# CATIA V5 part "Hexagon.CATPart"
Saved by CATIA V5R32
Part number: Hezagon
Bounding box of the stored display mesh (mm): x -50 to 50, y -43.301 to 43.301, z -50 to 50
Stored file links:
  D:\PROJECTS\Project 2022\CATIA V5 6R 2022\Resources\Part Files\c16_catia_v5_6r2022_prt\Cylindrical Joint(Fig16-18)\Hexagon.CATPart
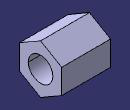
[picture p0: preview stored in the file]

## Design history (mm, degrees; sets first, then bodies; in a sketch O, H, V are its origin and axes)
Body1 (main body)
  Sketch1 on yz-plane, origin (0, 0, 0), H (0, 1, 0), V (0, 0, 1)
    point P1 (43.3013, -25)
    point P2 (43.3013, 25)
    point P3 (0, 50)
    point P4 (-43.3013, 25)
    point P5 (-43.3013, -25)
    point P6 (0, -50)
    point P7 (43.3013, 0)
    line L1 (43.3013, -25) -> (43.3013, 25)
    line L2 (43.3013, 25) -> (0, 50)
    line L3 (0, 50) -> (-43.3013, 25)
    line L4 (-43.3013, 25) -> (-43.3013, -25)
    line L5 (-43.3013, -25) -> (0, -50)
    line L6 (0, -50) -> (43.3013, -25)
    construction line L7 (0, 0) -> (43.3013, 0)
    construction circle A1 centre (0, 0) radius 50
    construction arc A2 centre (-43.3013, -25) radius 50 from (-43.3013, 25) to (0, -50) cw
    construction arc A3 centre (43.3013, 25) radius 50 from (0, 50) to (43.3013, -25) ccw
    circle A4 centre (0, 0) radius 25
    radius A4 = 25
    length L1 = 50
    horizontal: L7 H
    coincidence: A1 P1, A1 P2, A1 P3, A1 P4, A1 P5, A1 P6, A2 O, A3 O
    midpoint: P7 L1
    parallelism: L1 L4
  Pad1: profile Sketch1, direction (1, 0, 0), length 50, mirrored extent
